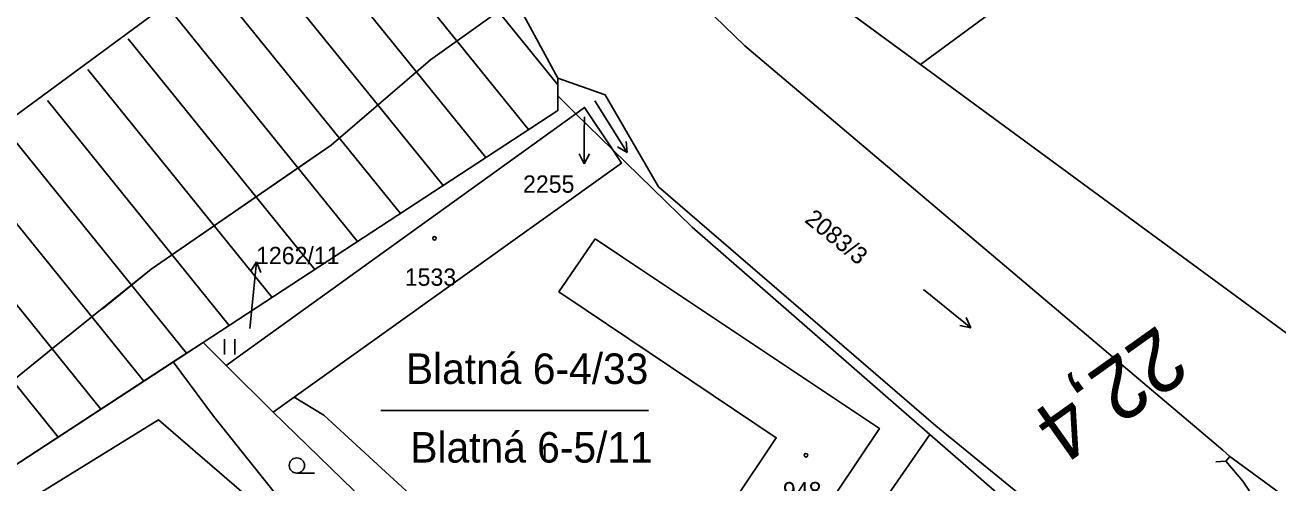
# Model space of a CAD drawing. Extents: x -794765 to -785424, y -1118958 to -1108731.
# Drawn here: x -792461.1 to -792337.7, y -1110007.1 to -1109962.1 of the extents above; entities that cross this region are included whole.
import ezdxf

# ---------------------------------------------------------------- set-up
doc = ezdxf.new("R2010")
doc.units = 0
for name, color, linetype in [('Level 66', 7, 'Continuous'), ('Level 73', 7, 'Continuous'), ('Level 75', 7, 'Continuous'), ('Level 76', 7, 'Continuous'), ('Level 77', 7, 'Continuous'), ('Level 78', 7, 'Continuous'), ('Level 79', 7, 'Continuous'), ('Level 80', 7, 'Continuous'), ('Level 81', 7, 'Continuous'), ('Vrstva 1', 7, 'Continuous'), ('Vrstva 53', 7, 'Continuous')]:
    doc.layers.add(name, color=color, linetype=linetype)

msp = doc.modelspace()

# ---------------------------------------------------------------- linework, layer by layer
at = {"layer": 'Level 66'}
for p, q in [((-792404.97, -1109969.55), (-792401.79, -1109974.64)), ((-792401.79, -1109974.64), (-792402.73, -1109974.08)), ((-792401.79, -1109974.64), (-792401.88, -1109973.55)), ((-792372.64, -1109988.09), (-792367.98, -1109991.86)), ((-792367.98, -1109991.86), (-792369.06, -1109991.64)), ((-792367.98, -1109991.86), (-792368.42, -1109990.86)), ((-792441.42, -1109994.49), (-792441.42, -1109992.99)), ((-792440.42, -1109994.49), (-792440.42, -1109992.99)), ((-792409.89, -1110004.89), (-792409.89, -1110003.39)), ((-792408.89, -1110004.89), (-792408.89, -1110003.39)), ((-792434.3, -1110006.15), (-792432.55, -1110006.15))]:
    msp.add_line(p, q, dxfattribs=at)
msp.add_circle((-792434.3, -1110005.4), 0.75, dxfattribs=at)
at = {"layer": 'Level 75'}
for p, q in [((-792350, -1109949.1), (-792372.92, -1109965.97)), ((-792372.92, -1109965.97), (-792383.68, -1109958.07)), ((-792408.62, -1109969.07), (-792408.62, -1109967.32)), ((-792408.62, -1109969.07), (-792406.84, -1109970.81)), ((-792406.84, -1109970.81), (-792441.26, -1109995.57)), ((-792403.21, -1109974.35), (-792406.84, -1109970.81)), ((-792404.94, -1109983.1), (-792408.53, -1109988.32)), ((-792441.26, -1109995.57), (-792443.53, -1109993.3)), ((-792441.26, -1109995.57), (-792436.64, -1110000.17)), ((-792436.64, -1110000.17), (-792434.57, -1109998.69)), ((-792372, -1110002.35), (-792395.89, -1110036.68))]:
    msp.add_line(p, q, dxfattribs=at)
for points in [[(-792424.33, -1109945.11), (-792427.01, -1109945.27), (-792468.07, -1109975.45)], [(-792424.33, -1109945.11), (-792418.77, -1109951.27), (-792418.22, -1109951.87), (-792417.83, -1109951.51), (-792412.51, -1109959), (-792413, -1109959.27), (-792412.59, -1109960.02), (-792408.62, -1109967.32)], [(-792396.21, -1109958.32), (-792390.22, -1109964.13), (-792343.17, -1110003.9), (-792342.46, -1110004.5), (-792325.49, -1110016.94)], [(-792310.79, -1110007.06), (-792329.62, -1109997.74), (-792372.92, -1109965.97)], [(-792408.62, -1109967.32), (-792403.95, -1109968.95), (-792398.71, -1109978), (-792371.41, -1110001.5), (-792362.62, -1110008.67), (-792349.7, -1110025.75)], [(-792443.53, -1109993.3), (-792408.62, -1109970.51), (-792408.62, -1109969.07)], [(-792406.84, -1109970.81), (-792405.98, -1109970.19), (-792403.21, -1109974.35)], [(-792434.57, -1109998.69), (-792402.34, -1109975.66), (-792403.21, -1109974.35)], [(-792372, -1110002.35), (-792395.41, -1109981.97), (-792403.21, -1109974.35)], [(-792408.53, -1109988.32), (-792405.83, -1109990.13), (-792387.11, -1110002.67), (-792400.35, -1110022.45), (-792393.81, -1110026.88), (-792376.96, -1110001.77), (-792402.24, -1109984.9), (-792404.94, -1109983.1)], [(-792443.53, -1109993.3), (-792471.37, -1110011.46), (-792501.89, -1110034.83), (-792516.81, -1110049.41)], [(-792434.57, -1109998.69), (-792431.65, -1110000.44), (-792421.95, -1110009.35), (-792406.84, -1110026.2), (-792395.89, -1110036.68)], [(-792397.13, -1110038.47), (-792417.45, -1110018.77), (-792436.64, -1110000.17)], [(-792470.94, -1110015.11), (-792447.93, -1110000.91), (-792439.75, -1110007.97)], [(-792349.7, -1110025.75), (-792355.19, -1110021.33), (-792363.15, -1110010.05), (-792372, -1110002.35)]]:
    msp.add_lwpolyline(points, dxfattribs=at)
at = {"layer": 'Level 77'}
for p, q in [((-792343.86, -1110005.04), (-792342.86, -1110004.97)), ((-792342.46, -1110004.5), (-792342.86, -1110004.97)), ((-792342.86, -1110004.97), (-792341.19, -1110006.95)), ((-792341.19, -1110006.95), (-792339.76, -1110009.11))]:
    msp.add_line(p, q, dxfattribs=at)
at = {"layer": 'Level 78'}
for p, q in [((-792408.62, -1109967.98), (-792427.01, -1109945.27)), ((-792411.49, -1109972.38), (-792430.99, -1109948.3)), ((-792415.7, -1109975.13), (-792434.97, -1109951.33)), ((-792419.91, -1109977.88), (-792438.95, -1109954.36)), ((-792424.11, -1109980.63), (-792442.93, -1109957.39)), ((-792428.32, -1109983.37), (-792446.91, -1109960.42)), ((-792432.53, -1109986.12), (-792450.89, -1109963.45)), ((-792436.74, -1109988.87), (-792454.87, -1109966.48)), ((-792440.95, -1109991.62), (-792458.85, -1109969.51)), ((-792445.16, -1109994.36), (-792462.83, -1109972.54)), ((-792449.37, -1109997.11), (-792466.81, -1109975.57)), ((-792453.58, -1109999.86), (-792470.79, -1109978.6)), ((-792457.79, -1110002.6), (-792474.77, -1109981.63))]:
    msp.add_line(p, q, dxfattribs=at)
at = {"layer": 'Level 79'}
for centre in [(-792420.75, -1109983.06), (-792384.19, -1110004.39)]:
    msp.add_circle(centre, 0.175, dxfattribs=at)
at = {"layer": 'Level 80'}
for p, q in [((-792406, -1109971.13), (-792406.01, -1109972.75)), ((-792406.01, -1109972.75), (-792406.01, -1109975.75)), ((-792406.01, -1109975.75), (-792406.51, -1109974.75)), ((-792406.01, -1109975.75), (-792405.51, -1109974.75)), ((-792438.26, -1109985.39), (-792438.86, -1109986.33)), ((-792438.57, -1109988.37), (-792438.26, -1109985.39)), ((-792438.26, -1109985.39), (-792437.86, -1109986.43)), ((-792438.94, -1109991.94), (-792438.57, -1109988.37))]:
    msp.add_line(p, q, dxfattribs=at)
at = {"layer": 'Level 81'}
for points in [[(-792329.62, -1109997.74), (-792372.92, -1109965.97), (-792383.68, -1109958.07), (-792389.98, -1109953.44), (-792394.9, -1109948.21), (-792395.36, -1109947.72), (-792395.96, -1109947.08), (-792396.36, -1109947.46), (-792401.63, -1109940.01), (-792401.09, -1109939.74), (-792401.42, -1109939.07), (-792404.43, -1109932.95), (-792404.35, -1109930.54), (-792406.09, -1109932.53), (-792409.46, -1109929.26), (-792407.99, -1109927.32), (-792424.2, -1109907.16), (-792385.97, -1109878.06), (-792389.09, -1109874.23), (-792363.55, -1109861.57), (-792349.96, -1109854.83), (-792346.23, -1109853.43), (-792326.43, -1109839.17)], [(-792420.88, -1109932.17), (-792420.03, -1109934.77), (-792419.01, -1109935.88), (-792417.84, -1109933.35), (-792408.74, -1109944.21), (-792405.73, -1109947.8), (-792402.71, -1109951.72), (-792401.99, -1109952.45), (-792396.21, -1109958.32), (-792390.22, -1109964.13), (-792343.17, -1110003.9), (-792342.46, -1110004.5), (-792325.49, -1110016.94), (-792320.64, -1110020.43), (-792321.4, -1110021.63), (-792321.36, -1110021.79), (-792318.97, -1110023.02), (-792307.95, -1110029.74), (-792289.1, -1110038.19), (-792276.39, -1110054.16)], [(-792446.47, -1109995.21), (-792443.53, -1109993.3), (-792408.62, -1109970.51), (-792408.62, -1109969.07), (-792406.84, -1109970.81), (-792403.21, -1109974.35), (-792395.41, -1109981.97), (-792372, -1110002.35), (-792363.15, -1110010.05), (-792355.19, -1110021.33), (-792349.7, -1110025.75), (-792348.65, -1110027.13), (-792346.31, -1110028.51), (-792338.95, -1110033.41), (-792333.76, -1110037.48), (-792294.56, -1110068.22), (-792309.21, -1110070.53), (-792340.62, -1110085.93)], [(-792446.47, -1109995.21), (-792471.37, -1110011.46), (-792501.89, -1110034.83), (-792516.81, -1110049.41), (-792519.67, -1110052.2), (-792521.55, -1110054.04), (-792524.19, -1110057.53), (-792546.69, -1110087.26)], [(-792446.47, -1109995.21), (-792442.52, -1110000.55), (-792434.17, -1110010.96), (-792407.54, -1110033.08), (-792398.1, -1110039.65), (-792396.54, -1110040.74), (-792391.47, -1110045.84), (-792372.77, -1110060.44), (-792369.41, -1110063.06), (-792360.99, -1110069.63), (-792353.85, -1110075.2), (-792340.62, -1110085.93)]]:
    msp.add_lwpolyline(points, dxfattribs=at)
at = {"layer": 'Vrstva 1'}
for p, q in [((-792401.43, -1109951.47), (-792421.14, -1109965.5)), ((-792421.14, -1109965.5), (-792430.91, -1109973.9)), ((-792430.91, -1109973.9), (-792448.63, -1109986.11)), ((-792448.63, -1109986.11), (-792453.43, -1109989.98)), ((-792399.68, -1110000), (-792426.03, -1110000))]:
    msp.add_line(p, q, dxfattribs=at)
msp.add_lwpolyline([(-792430.91, -1109973.9), (-792434.36, -1109976.27), (-792448.63, -1109986.11), (-792458.31, -1109993.87), (-792466.72, -1110000.66)], dxfattribs=at)
at = {"layer": 'Vrstva 53'}
for points in [[(-792619.92, -1110077.28), (-792614.54, -1110062.94), (-792603.7, -1110040.3), (-792590.28, -1110048.67), (-792575.7, -1110052.69), (-792570.38, -1110049.94), (-792547.64, -1110038.22), (-792537.18, -1110032.76), (-792484.01, -1109988.67), (-792468.07, -1109975.45), (-792427.01, -1109945.27)], [(-792412.59, -1109960.02), (-792408.62, -1109967.32), (-792408.62, -1109969.07), (-792408.62, -1109970.51), (-792443.53, -1109993.3), (-792471.37, -1110011.46), (-792501.89, -1110034.83), (-792516.81, -1110049.41), (-792519.67, -1110052.2), (-792521.55, -1110054.04), (-792524.19, -1110057.53), (-792546.69, -1110087.26), (-792553.88, -1110099.37), (-792562.99, -1110114.71), (-792563.49, -1110115.56), (-792579.9, -1110146.2), (-792584.67, -1110156.97), (-792585.44, -1110159.39), (-792598.98, -1110199.86)]]:
    msp.add_lwpolyline(points, dxfattribs=at)

# ---------------------------------------------------------------- texts
at = {"layer": 'Level 73'}
msp.add_text('22,4', height=6, rotation=215.3609, dxfattribs=at).set_placement((-792349.52, -1109991.48))
at = {"layer": 'Level 76'}
for s, p in [('2255', (-792412.04, -1109978.58)), ('1262/11', (-792438.32, -1109985.6)), ('1533', (-792423.68, -1109987.73)), ('948', (-792386.46, -1110008.72))]:
    msp.add_text(s, height=1.7, dxfattribs=at).set_placement(p)
msp.add_text('2083/3', height=1.7, rotation=321, dxfattribs=at).set_placement((-792384.42, -1109981.39))
at = {"layer": 'Vrstva 1'}
for s, p in [('Blatná 6-4/33', (-792423.57, -1109997.38)), ('Blatná 6-5/11', (-792423.14, -1110005.11))]:
    msp.add_text(s, height=3, dxfattribs=at).set_placement(p)

doc.saveas('drawing.dxf')
